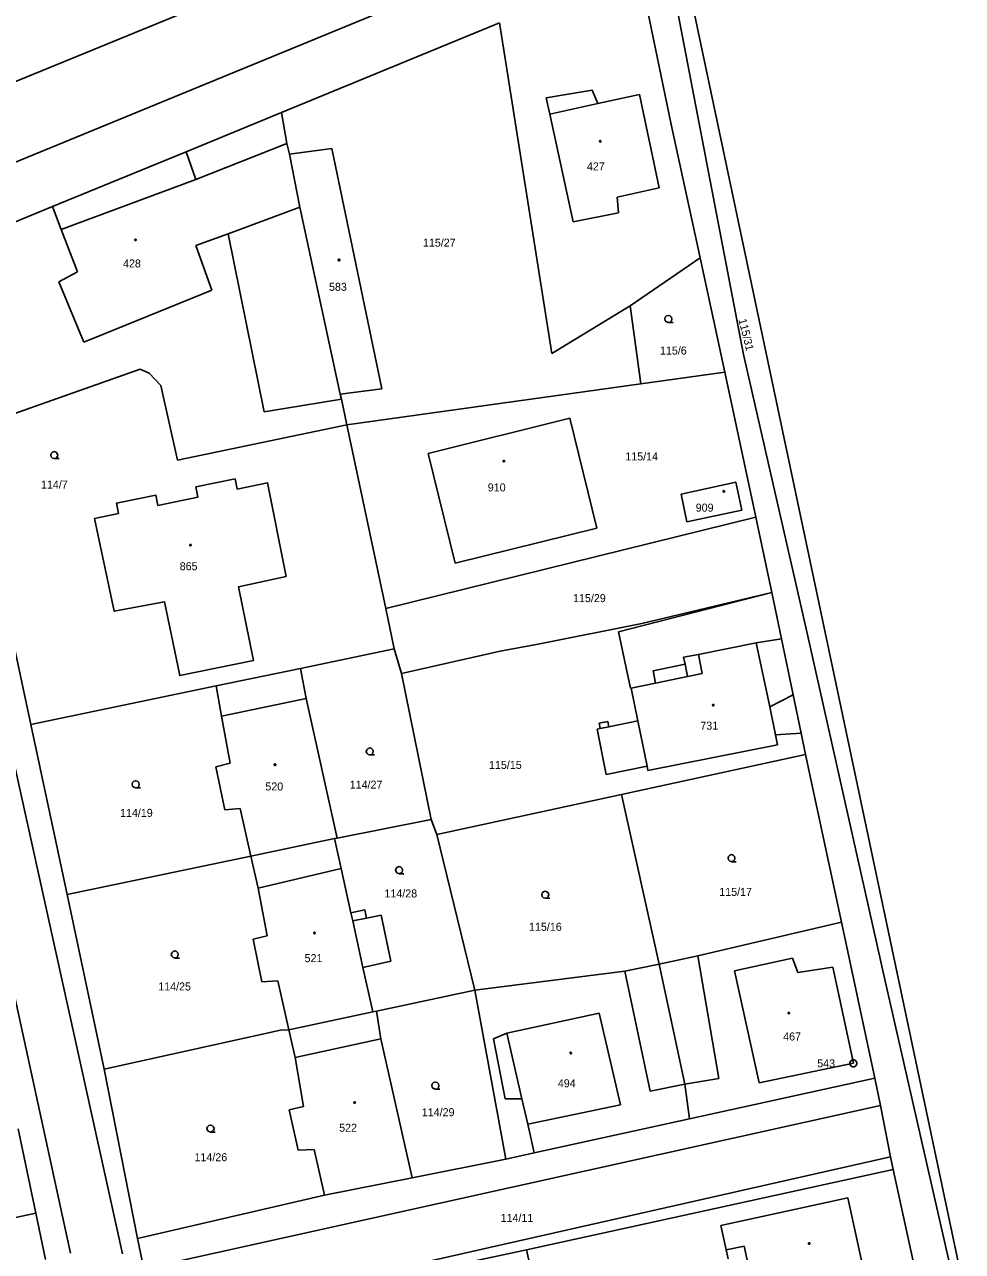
# Model space of a CAD drawing. Extents: x -757994 to -755874, y -1047691 to -1046119.
# Drawn here: x -756380.5 to -756280.8, y -1046878.4 to -1046748.1 of the extents above; entities that cross this region are included whole.
import ezdxf

# ---------------------------------------------------------------- set-up
doc = ezdxf.new("R2010")
doc.units = 0
doc.layers.add('katastrální mapa', color=7, linetype='Continuous')

msp = doc.modelspace()

# ---------------------------------------------------------------- linework, layer by layer
at = {"layer": 'katastrální mapa'}
for p, q in [((-756396.18, -1046760.15), (-756307.54, -1046723.85)), ((-756391.74, -1046766.92), (-756311.94, -1046734.1)), ((-756312.17, -1046741.14), (-756304.11, -1046783.1)), ((-756310.63, -1046740.64), (-756269.78, -1046934.1)), ((-756314.53, -1046745.53), (-756311.78, -1046758.68)), ((-756330.03, -1046747.89), (-756353.18, -1046757.42)), ((-756324.46, -1046783.01), (-756330.03, -1046747.89)), ((-756325.07, -1046755.85), (-756320.17, -1046755.03)), ((-756320.17, -1046755.03), (-756319.58, -1046756.47)), ((-756324.69, -1046757.59), (-756325.07, -1046755.85)), ((-756319.58, -1046756.47), (-756324.69, -1046757.59)), ((-756319.58, -1046756.47), (-756315.15, -1046755.5)), ((-756315.15, -1046755.5), (-756313.05, -1046765.41)), ((-756353.18, -1046757.42), (-756363.33, -1046761.6)), ((-756352.62, -1046760.71), (-756353.18, -1046757.42)), ((-756322.21, -1046769.04), (-756324.69, -1046757.59)), ((-756311.78, -1046758.68), (-756308.69, -1046772.83)), ((-756363.33, -1046761.6), (-756377.5, -1046767.39)), ((-756362.27, -1046764.52), (-756363.33, -1046761.6)), ((-756362.27, -1046764.52), (-756352.62, -1046760.71)), ((-756352.33, -1046761.84), (-756352.62, -1046760.71)), ((-756347.84, -1046761.25), (-756352.33, -1046761.84)), ((-756351.23, -1046767.48), (-756352.33, -1046761.84)), ((-756342.54, -1046786.77), (-756347.84, -1046761.25)), ((-756376.58, -1046769.83), (-756362.27, -1046764.52)), ((-756313.05, -1046765.41), (-756317.51, -1046766.41)), ((-756317.51, -1046766.41), (-756317.38, -1046768.06)), ((-756377.5, -1046767.39), (-756390.34, -1046772.66)), ((-756376.58, -1046769.83), (-756377.5, -1046767.39)), ((-756351.23, -1046767.48), (-756358.86, -1046770.29)), ((-756346.94, -1046787.33), (-756351.23, -1046767.48)), ((-756317.38, -1046768.06), (-756322.21, -1046769.04)), ((-756374.87, -1046774.35), (-756376.58, -1046769.83)), ((-756358.86, -1046770.29), (-756362.3, -1046771.52)), ((-756355.03, -1046789.2), (-756358.86, -1046770.29)), ((-756362.3, -1046771.52), (-756360.6, -1046776.28)), ((-756308.69, -1046772.83), (-756316.16, -1046777.96)), ((-756306.09, -1046784.99), (-756308.69, -1046772.83)), ((-756393.26, -1046773.82), (-756370.08, -1046878.6)), ((-756376.85, -1046775.39), (-756374.87, -1046774.35)), ((-756375.61, -1046878.54), (-756398, -1046775.71)), ((-756374.2, -1046781.8), (-756376.85, -1046775.39)), ((-756360.6, -1046776.28), (-756374.2, -1046781.8)), ((-756316.16, -1046777.96), (-756324.46, -1046783.01)), ((-756316.16, -1046777.96), (-756315, -1046786.23)), ((-756304.11, -1046783.1), (-756297.34, -1046812.7)), ((-756386.52, -1046791.13), (-756368.21, -1046784.66)), ((-756368.21, -1046784.66), (-756367.23, -1046785.08)), ((-756367.23, -1046785.08), (-756366, -1046786.39)), ((-756306.09, -1046784.99), (-756315, -1046786.23)), ((-756302.8, -1046800.38), (-756306.09, -1046784.99)), ((-756366, -1046786.39), (-756364.24, -1046794.32)), ((-756315, -1046786.23), (-756346.26, -1046790.59)), ((-756346.81, -1046787.86), (-756355.03, -1046789.2)), ((-756346.94, -1046787.33), (-756342.54, -1046786.77)), ((-756346.81, -1046787.86), (-756346.94, -1046787.33)), ((-756346.26, -1046790.59), (-756346.81, -1046787.86)), ((-756364.24, -1046794.32), (-756346.26, -1046790.59)), ((-756342.11, -1046810.08), (-756346.26, -1046790.59)), ((-756322.56, -1046789.87), (-756337.61, -1046793.62)), ((-756319.68, -1046801.54), (-756322.56, -1046789.87)), ((-756379.8, -1046822.39), (-756386.52, -1046791.13)), ((-756337.61, -1046793.62), (-756334.72, -1046805.28)), ((-756310.74, -1046797.96), (-756304.91, -1046796.68)), ((-756304.91, -1046796.68), (-756304.28, -1046799.63)), ((-756310.12, -1046800.87), (-756310.74, -1046797.96)), ((-756304.28, -1046799.63), (-756310.12, -1046800.87)), ((-756342.11, -1046810.08), (-756302.8, -1046800.38)), ((-756301.09, -1046808.37), (-756302.8, -1046800.38)), ((-756334.72, -1046805.28), (-756319.68, -1046801.54)), ((-756317.37, -1046812.57), (-756301.09, -1046808.37)), ((-756301.09, -1046808.37), (-756314.91, -1046811.68)), ((-756300.07, -1046813.29), (-756301.09, -1046808.37)), ((-756341.2, -1046814.37), (-756342.11, -1046810.08)), ((-756314.91, -1046811.68), (-756325.75, -1046813.82)), ((-756316.12, -1046818.56), (-756317.37, -1046812.57)), ((-756297.34, -1046812.7), (-756289.01, -1046849.81)), ((-756325.75, -1046813.82), (-756329.96, -1046814.63)), ((-756302.74, -1046813.73), (-756308.89, -1046814.96)), ((-756302.74, -1046813.73), (-756300.07, -1046813.29)), ((-756301.32, -1046820.54), (-756302.74, -1046813.73)), ((-756298.82, -1046819.26), (-756300.07, -1046813.29)), ((-756351.16, -1046816.44), (-756341.2, -1046814.37)), ((-756340.44, -1046816.99), (-756341.2, -1046814.37)), ((-756329.96, -1046814.63), (-756340.44, -1046816.99)), ((-756308.89, -1046814.96), (-756310.46, -1046815.27)), ((-756310.46, -1046815.27), (-756310.31, -1046816)), ((-756308.5, -1046817), (-756308.89, -1046814.96)), ((-756360.14, -1046818.3), (-756351.16, -1046816.44)), ((-756351.16, -1046816.44), (-756350.58, -1046819.64)), ((-756310.31, -1046816), (-756313.71, -1046816.7)), ((-756313.71, -1046816.7), (-756313.44, -1046818.01)), ((-756310.04, -1046817.32), (-756310.31, -1046816)), ((-756337.27, -1046832.48), (-756340.44, -1046816.99)), ((-756313.44, -1046818.01), (-756316.02, -1046818.54)), ((-756313.44, -1046818.01), (-756310.04, -1046817.32)), ((-756310.04, -1046817.32), (-756308.5, -1046817)), ((-756379.8, -1046822.39), (-756360.14, -1046818.3)), ((-756360.14, -1046818.3), (-756359.55, -1046821.52)), ((-756316.02, -1046818.54), (-756316.12, -1046818.56)), ((-756316.02, -1046818.54), (-756315.32, -1046822.02)), ((-756301.32, -1046820.54), (-756298.82, -1046819.26)), ((-756297.98, -1046823.34), (-756298.82, -1046819.26)), ((-756359.55, -1046821.52), (-756350.58, -1046819.64)), ((-756350.58, -1046819.64), (-756347.26, -1046834.46)), ((-756300.7, -1046823.49), (-756301.32, -1046820.54)), ((-756359.55, -1046821.52), (-756358.63, -1046826.51)), ((-756375.96, -1046840.46), (-756379.8, -1046822.39)), ((-756319.33, -1046822.83), (-756319.65, -1046822.9)), ((-756319.65, -1046822.9), (-756318.7, -1046827.73)), ((-756318.51, -1046822.07), (-756319.44, -1046822.26)), ((-756319.44, -1046822.26), (-756319.33, -1046822.83)), ((-756319.33, -1046822.83), (-756318.4, -1046822.65)), ((-756318.4, -1046822.65), (-756318.51, -1046822.07)), ((-756315.32, -1046822.02), (-756318.4, -1046822.65)), ((-756315.32, -1046822.02), (-756314.35, -1046826.83)), ((-756300.7, -1046823.49), (-756297.98, -1046823.34)), ((-756300.48, -1046824.57), (-756300.7, -1046823.49)), ((-756297.51, -1046825.58), (-756297.98, -1046823.34)), ((-756297.51, -1046825.58), (-756317.05, -1046829.82)), ((-756314.26, -1046827.28), (-756300.48, -1046824.57)), ((-756293.69, -1046843.39), (-756297.51, -1046825.58)), ((-756358.63, -1046826.51), (-756360.17, -1046826.9)), ((-756360.17, -1046826.9), (-756359.22, -1046831.48)), ((-756318.7, -1046827.73), (-756314.35, -1046826.83)), ((-756314.35, -1046826.83), (-756314.26, -1046827.28)), ((-756317.05, -1046829.82), (-756336.69, -1046834.09)), ((-756313.07, -1046847.85), (-756317.05, -1046829.82)), ((-756359.22, -1046831.48), (-756357.56, -1046831.31)), ((-756357.56, -1046831.31), (-756356.44, -1046836.38)), ((-756347.26, -1046834.46), (-756337.27, -1046832.48)), ((-756336.69, -1046834.09), (-756337.27, -1046832.48)), ((-756356.44, -1046836.38), (-756347.56, -1046834.52)), ((-756347.56, -1046834.52), (-756347.26, -1046834.46)), ((-756346.86, -1046837.7), (-756347.56, -1046834.52)), ((-756332.66, -1046850.6), (-756336.69, -1046834.09)), ((-756375.96, -1046840.46), (-756356.44, -1046836.38)), ((-756355.68, -1046839.79), (-756356.44, -1046836.38)), ((-756346.86, -1046837.7), (-756355.68, -1046839.79)), ((-756345.81, -1046842.42), (-756346.86, -1046837.7)), ((-756354.72, -1046844.86), (-756355.68, -1046839.79)), ((-756372.02, -1046859.01), (-756375.96, -1046840.46)), ((-756344.34, -1046842.1), (-756345.81, -1046842.42)), ((-756345.81, -1046842.42), (-756345.62, -1046843.27)), ((-756344.15, -1046842.96), (-756344.34, -1046842.1)), ((-756342.61, -1046842.64), (-756344.15, -1046842.96)), ((-756341.57, -1046847.54), (-756342.61, -1046842.64)), ((-756345.62, -1046843.27), (-756344.15, -1046842.96)), ((-756345.62, -1046843.27), (-756344.53, -1046848.22)), ((-756293.69, -1046843.39), (-756308.97, -1046846.98)), ((-756290.14, -1046859.97), (-756293.69, -1046843.39)), ((-756356.21, -1046845.21), (-756354.72, -1046844.86)), ((-756355.26, -1046849.72), (-756356.21, -1046845.21)), ((-756344.53, -1046848.22), (-756341.57, -1046847.54)), ((-756313.07, -1046847.85), (-756316.72, -1046848.59)), ((-756308.97, -1046846.98), (-756313.07, -1046847.85)), ((-756313.07, -1046847.85), (-756310.34, -1046860.6)), ((-756306.73, -1046859.98), (-756308.97, -1046846.98)), ((-756305.05, -1046848.55), (-756298.89, -1046847.21)), ((-756298.89, -1046847.21), (-756298.34, -1046848.73)), ((-756343.62, -1046852.29), (-756344.53, -1046848.22)), ((-756316.72, -1046848.59), (-756332.66, -1046850.6)), ((-756316.72, -1046848.59), (-756314.03, -1046861.33)), ((-756302.43, -1046860.45), (-756305.05, -1046848.55)), ((-756298.34, -1046848.73), (-756294.62, -1046848.19)), ((-756294.62, -1046848.19), (-756292.42, -1046858.38)), ((-756353.57, -1046849.62), (-756355.26, -1046849.72)), ((-756352.41, -1046854.82), (-756353.57, -1046849.62)), ((-756289.01, -1046849.81), (-756269.04, -1046937.62)), ((-756343.1, -1046852.83), (-756332.66, -1046850.6)), ((-756329.34, -1046868.55), (-756332.66, -1046850.6)), ((-756352.41, -1046854.82), (-756343.48, -1046852.91)), ((-756343.48, -1046852.91), (-756343.62, -1046852.29)), ((-756343.48, -1046852.91), (-756343.1, -1046852.83)), ((-756343.1, -1046852.83), (-756342.62, -1046855.79)), ((-756329.23, -1046855.18), (-756319.44, -1046853.06)), ((-756319.44, -1046853.06), (-756317.16, -1046862.78)), ((-756372.02, -1046859.01), (-756353.29, -1046854.85)), ((-756353.29, -1046854.85), (-756352.41, -1046854.82)), ((-756352.41, -1046854.82), (-756351.75, -1046857.75)), ((-756351.75, -1046857.75), (-756342.62, -1046855.79)), ((-756342.62, -1046855.79), (-756339.31, -1046870.53)), ((-756330.67, -1046855.77), (-756329.23, -1046855.18)), ((-756329.42, -1046862.17), (-756330.67, -1046855.77)), ((-756329.23, -1046855.18), (-756327.66, -1046862.16)), ((-756351.75, -1046857.75), (-756350.83, -1046862.97)), ((-756292.42, -1046858.38), (-756302.43, -1046860.45)), ((-756292.45, -1046858.38), (-756292.4, -1046858.38)), ((-756368.48, -1046876.97), (-756372.02, -1046859.01)), ((-756314.03, -1046861.33), (-756310.34, -1046860.6)), ((-756310.34, -1046860.6), (-756306.73, -1046859.98)), ((-756310.34, -1046860.6), (-756309.84, -1046864.27)), ((-756290.14, -1046859.97), (-756309.84, -1046864.27)), ((-756289.56, -1046862.86), (-756290.14, -1046859.97)), ((-756327.66, -1046862.16), (-756329.42, -1046862.17)), ((-756327.03, -1046864.85), (-756327.66, -1046862.16)), ((-756367.82, -1046880.2), (-756289.56, -1046862.86)), ((-756350.83, -1046862.97), (-756352.38, -1046863.32)), ((-756352.38, -1046863.32), (-756351.4, -1046867.59)), ((-756317.16, -1046862.78), (-756327.03, -1046864.85)), ((-756288.48, -1046868.3), (-756289.56, -1046862.86)), ((-756327.03, -1046864.85), (-756326.34, -1046867.89)), ((-756309.84, -1046864.27), (-756326.34, -1046867.89)), ((-756381.17, -1046865.34), (-756379.28, -1046874.3)), ((-756351.4, -1046867.59), (-756349.71, -1046867.53)), ((-756349.71, -1046867.53), (-756348.6, -1046872.37)), ((-756288.48, -1046868.3), (-756366.64, -1046885.96)), ((-756339.31, -1046870.53), (-756329.34, -1046868.55)), ((-756326.34, -1046867.89), (-756329.34, -1046868.55)), ((-756288.21, -1046869.66), (-756288.48, -1046868.3)), ((-756288.21, -1046869.66), (-756327.17, -1046878.19)), ((-756284.47, -1046886.76), (-756288.21, -1046869.66)), ((-756348.6, -1046872.37), (-756339.31, -1046870.53)), ((-756368.48, -1046876.97), (-756348.6, -1046872.37)), ((-756293.02, -1046872.66), (-756306.51, -1046875.61)), ((-756291.13, -1046881.27), (-756293.02, -1046872.66)), ((-756379.28, -1046874.3), (-756385.1, -1046875.55)), ((-756379.28, -1046874.3), (-756378.24, -1046879.22)), ((-756306.51, -1046875.61), (-756305.94, -1046878.2)), ((-756367.82, -1046880.2), (-756368.48, -1046876.97)), ((-756305.94, -1046878.2), (-756304.02, -1046877.8)), ((-756304.02, -1046877.8), (-756303.52, -1046880.1)), ((-756327.17, -1046878.19), (-756349.56, -1046882.95)), ((-756323.13, -1046895.69), (-756327.17, -1046878.19)), ((-756305.94, -1046878.2), (-756305.74, -1046879.13))]:
    msp.add_line(p, q, dxfattribs=at)
for points in [[(-756319.33, -1046760.39), (-756319.28, -1046760.4), (-756319.25, -1046760.44), (-756319.24, -1046760.47), (-756319.25, -1046760.51), (-756319.29, -1046760.55), (-756319.33, -1046760.55), (-756319.38, -1046760.54), (-756319.41, -1046760.51), (-756319.42, -1046760.47), (-756319.41, -1046760.43), (-756319.36, -1046760.39)], [(-756368.7, -1046770.86), (-756368.65, -1046770.87), (-756368.62, -1046770.91), (-756368.61, -1046770.94), (-756368.62, -1046770.98), (-756368.67, -1046771.02), (-756368.7, -1046771.02), (-756368.74, -1046771.01), (-756368.77, -1046770.98), (-756368.78, -1046770.94), (-756368.77, -1046770.9), (-756368.73, -1046770.86)], [(-756347.08, -1046772.99), (-756347.03, -1046773), (-756347, -1046773.05), (-756346.99, -1046773.08), (-756347, -1046773.12), (-756347.04, -1046773.16), (-756347.08, -1046773.17), (-756347.12, -1046773.15), (-756347.16, -1046773.12), (-756347.17, -1046773.08), (-756347.16, -1046773.03), (-756347.11, -1046773)], [(-756329.56, -1046794.36), (-756329.51, -1046794.37), (-756329.49, -1046794.41), (-756329.48, -1046794.44), (-756329.49, -1046794.48), (-756329.53, -1046794.52), (-756329.56, -1046794.52), (-756329.6, -1046794.51), (-756329.64, -1046794.48), (-756329.65, -1046794.44), (-756329.64, -1046794.4), (-756329.6, -1046794.36)], [(-756373.06, -1046800.52), (-756370.51, -1046799.98), (-756370.73, -1046798.9), (-756366.54, -1046798.04), (-756366.32, -1046799.13), (-756362.06, -1046798.26), (-756362.28, -1046797.18), (-756358.11, -1046796.32), (-756357.88, -1046797.41), (-756354.68, -1046796.74), (-756352.69, -1046806.69), (-756357.75, -1046807.77), (-756356.17, -1046815.6), (-756364, -1046817.21), (-756365.63, -1046809.37), (-756370.96, -1046810.37)], [(-756306.2, -1046797.57), (-756306.15, -1046797.58), (-756306.12, -1046797.62), (-756306.11, -1046797.65), (-756306.12, -1046797.7), (-756306.17, -1046797.73), (-756306.2, -1046797.74), (-756306.24, -1046797.72), (-756306.27, -1046797.69), (-756306.28, -1046797.65), (-756306.27, -1046797.61), (-756306.23, -1046797.57)], [(-756362.78, -1046803.35), (-756362.79, -1046803.4), (-756362.83, -1046803.43), (-756362.86, -1046803.43), (-756362.91, -1046803.43), (-756362.94, -1046803.38), (-756362.94, -1046803.35), (-756362.93, -1046803.3), (-756362.9, -1046803.28), (-756362.86, -1046803.27), (-756362.81, -1046803.28), (-756362.78, -1046803.32)], [(-756307.31, -1046820.26), (-756307.26, -1046820.27), (-756307.24, -1046820.32), (-756307.23, -1046820.35), (-756307.24, -1046820.4), (-756307.28, -1046820.43), (-756307.31, -1046820.44), (-756307.35, -1046820.42), (-756307.39, -1046820.39), (-756307.4, -1046820.35), (-756307.39, -1046820.3), (-756307.35, -1046820.27)], [(-756353.87, -1046826.59), (-756353.82, -1046826.6), (-756353.79, -1046826.64), (-756353.78, -1046826.67), (-756353.79, -1046826.72), (-756353.84, -1046826.75), (-756353.87, -1046826.76), (-756353.92, -1046826.74), (-756353.95, -1046826.71), (-756353.96, -1046826.67), (-756353.95, -1046826.62), (-756353.91, -1046826.59)], [(-756349.69, -1046844.47), (-756349.64, -1046844.48), (-756349.61, -1046844.52), (-756349.6, -1046844.55), (-756349.61, -1046844.6), (-756349.66, -1046844.63), (-756349.69, -1046844.64), (-756349.73, -1046844.62), (-756349.76, -1046844.59), (-756349.77, -1046844.55), (-756349.76, -1046844.51), (-756349.72, -1046844.47)], [(-756299.29, -1046852.97), (-756299.24, -1046852.98), (-756299.22, -1046853.02), (-756299.21, -1046853.05), (-756299.22, -1046853.1), (-756299.26, -1046853.13), (-756299.29, -1046853.14), (-756299.34, -1046853.12), (-756299.36, -1046853.09), (-756299.38, -1046853.05), (-756299.36, -1046853.01), (-756299.33, -1046852.97)], [(-756322.46, -1046857.21), (-756322.41, -1046857.22), (-756322.39, -1046857.26), (-756322.38, -1046857.29), (-756322.39, -1046857.34), (-756322.43, -1046857.37), (-756322.46, -1046857.38), (-756322.5, -1046857.36), (-756322.53, -1046857.33), (-756322.54, -1046857.29), (-756322.53, -1046857.25), (-756322.49, -1046857.21)], [(-756292.33, -1046858.02), (-756292.16, -1046858.12), (-756292.06, -1046858.29), (-756292.06, -1046858.48), (-756292.16, -1046858.65), (-756292.33, -1046858.74), (-756292.52, -1046858.74), (-756292.69, -1046858.65), (-756292.79, -1046858.48), (-756292.79, -1046858.29), (-756292.69, -1046858.12), (-756292.52, -1046858.02)], [(-756345.42, -1046862.47), (-756345.37, -1046862.48), (-756345.35, -1046862.52), (-756345.34, -1046862.55), (-756345.35, -1046862.6), (-756345.39, -1046862.63), (-756345.42, -1046862.64), (-756345.47, -1046862.62), (-756345.5, -1046862.59), (-756345.51, -1046862.55), (-756345.5, -1046862.51), (-756345.46, -1046862.47)], [(-756297.12, -1046877.44), (-756297.07, -1046877.45), (-756297.04, -1046877.49), (-756297.03, -1046877.52), (-756297.04, -1046877.57), (-756297.09, -1046877.6), (-756297.12, -1046877.61), (-756297.17, -1046877.59), (-756297.2, -1046877.56), (-756297.21, -1046877.52), (-756297.2, -1046877.48), (-756297.16, -1046877.44)]]:
    msp.add_lwpolyline(points, close=True, dxfattribs=at)
for points in [[(-756312.08, -1046779.71), (-756312.27, -1046779.66), (-756312.41, -1046779.52), (-756312.46, -1046779.34), (-756312.41, -1046779.16), (-756312.27, -1046779.02), (-756312.09, -1046778.97), (-756311.9, -1046779.02), (-756311.76, -1046779.16), (-756311.72, -1046779.35), (-756311.76, -1046779.53), (-756311.9, -1046779.67), (-756312.09, -1046779.72), (-756311.59, -1046779.72)], [(-756377.31, -1046794.16), (-756377.5, -1046794.11), (-756377.64, -1046793.98), (-756377.69, -1046793.79), (-756377.64, -1046793.61), (-756377.5, -1046793.47), (-756377.32, -1046793.42), (-756377.13, -1046793.47), (-756377, -1046793.61), (-756376.95, -1046793.8), (-756377, -1046793.99), (-756377.13, -1046794.12), (-756377.32, -1046794.17), (-756376.82, -1046794.17)], [(-756343.8, -1046825.63), (-756343.99, -1046825.58), (-756344.12, -1046825.45), (-756344.18, -1046825.26), (-756344.12, -1046825.08), (-756343.99, -1046824.94), (-756343.81, -1046824.89), (-756343.62, -1046824.94), (-756343.49, -1046825.08), (-756343.44, -1046825.27), (-756343.49, -1046825.46), (-756343.62, -1046825.59), (-756343.81, -1046825.64), (-756343.31, -1046825.64)], [(-756368.67, -1046829.12), (-756368.86, -1046829.07), (-756369, -1046828.94), (-756369.05, -1046828.75), (-756369, -1046828.57), (-756368.86, -1046828.43), (-756368.68, -1046828.38), (-756368.49, -1046828.43), (-756368.35, -1046828.57), (-756368.31, -1046828.76), (-756368.35, -1046828.95), (-756368.49, -1046829.08), (-756368.68, -1046829.13), (-756368.18, -1046829.13)], [(-756305.37, -1046836.96), (-756305.56, -1046836.91), (-756305.7, -1046836.77), (-756305.74, -1046836.59), (-756305.7, -1046836.41), (-756305.56, -1046836.27), (-756305.38, -1046836.22), (-756305.19, -1046836.27), (-756305.05, -1046836.41), (-756305.01, -1046836.6), (-756305.05, -1046836.78), (-756305.19, -1046836.92), (-756305.38, -1046836.97), (-756304.88, -1046836.97)], [(-756340.69, -1046838.24), (-756340.88, -1046838.19), (-756341.01, -1046838.05), (-756341.07, -1046837.87), (-756341.01, -1046837.69), (-756340.88, -1046837.55), (-756340.7, -1046837.5), (-756340.51, -1046837.55), (-756340.38, -1046837.69), (-756340.33, -1046837.88), (-756340.38, -1046838.07), (-756340.51, -1046838.2), (-756340.7, -1046838.25), (-756340.2, -1046838.25)], [(-756325.16, -1046840.85), (-756325.35, -1046840.8), (-756325.49, -1046840.67), (-756325.54, -1046840.48), (-756325.49, -1046840.29), (-756325.35, -1046840.16), (-756325.17, -1046840.11), (-756324.98, -1046840.16), (-756324.85, -1046840.29), (-756324.8, -1046840.49), (-756324.85, -1046840.68), (-756324.98, -1046840.81), (-756325.17, -1046840.86), (-756324.67, -1046840.86)], [(-756364.51, -1046847.19), (-756364.7, -1046847.14), (-756364.84, -1046847), (-756364.89, -1046846.82), (-756364.84, -1046846.64), (-756364.7, -1046846.5), (-756364.52, -1046846.45), (-756364.33, -1046846.5), (-756364.2, -1046846.64), (-756364.15, -1046846.83), (-756364.2, -1046847.01), (-756364.33, -1046847.15), (-756364.52, -1046847.2), (-756364.02, -1046847.2)], [(-756336.84, -1046861.12), (-756337.03, -1046861.07), (-756337.17, -1046860.94), (-756337.22, -1046860.75), (-756337.17, -1046860.57), (-756337.03, -1046860.43), (-756336.85, -1046860.38), (-756336.66, -1046860.43), (-756336.52, -1046860.57), (-756336.48, -1046860.76), (-756336.52, -1046860.95), (-756336.66, -1046861.08), (-756336.85, -1046861.13), (-756336.35, -1046861.13)], [(-756360.72, -1046865.68), (-756360.91, -1046865.63), (-756361.04, -1046865.5), (-756361.1, -1046865.31), (-756361.04, -1046865.12), (-756360.91, -1046864.99), (-756360.73, -1046864.94), (-756360.54, -1046864.99), (-756360.41, -1046865.12), (-756360.35, -1046865.32), (-756360.41, -1046865.51), (-756360.54, -1046865.64), (-756360.73, -1046865.69), (-756360.23, -1046865.69)]]:
    msp.add_lwpolyline(points, dxfattribs=at)

# ---------------------------------------------------------------- texts
for s, p in [('427', (-756320.74, -1046763.56)), ('115/27', (-756338.16, -1046771.66)), ('428', (-756370.02, -1046773.87)), ('583', (-756348.14, -1046776.35)), ('115/6', (-756312.98, -1046783.12)), ('115/14', (-756316.66, -1046794.36)), ('114/7', (-756378.74, -1046797.35)), ('910', (-756331.27, -1046797.65)), ('909', (-756309.18, -1046799.8)), ('865', (-756364, -1046806.02)), ('115/29', (-756322.21, -1046809.41)), ('731', (-756308.69, -1046822.95)), ('115/15', (-756331.14, -1046827.12)), ('114/27', (-756345.94, -1046829.22)), ('520', (-756354.9, -1046829.41)), ('114/19', (-756370.34, -1046832.21)), ('114/28', (-756342.25, -1046840.77)), ('115/17', (-756306.68, -1046840.6)), ('115/16', (-756326.89, -1046844.31)), ('521', (-756350.73, -1046847.64)), ('114/25', (-756366.28, -1046850.65)), ('467', (-756299.89, -1046855.96)), ('543', (-756296.27, -1046858.81)), ('494', (-756323.83, -1046860.93)), ('114/29', (-756338.28, -1046864)), ('522', (-756347.06, -1046865.65)), ('114/26', (-756362.43, -1046868.78)), ('114/11', (-756329.91, -1046875.22))]:
    msp.add_text(s, height=0.85, dxfattribs=at).set_placement(p)
msp.add_text('115/31', height=0.85, rotation=284.1871, dxfattribs=at).set_placement((-756304.65, -1046779.41))

doc.saveas('drawing.dxf')
